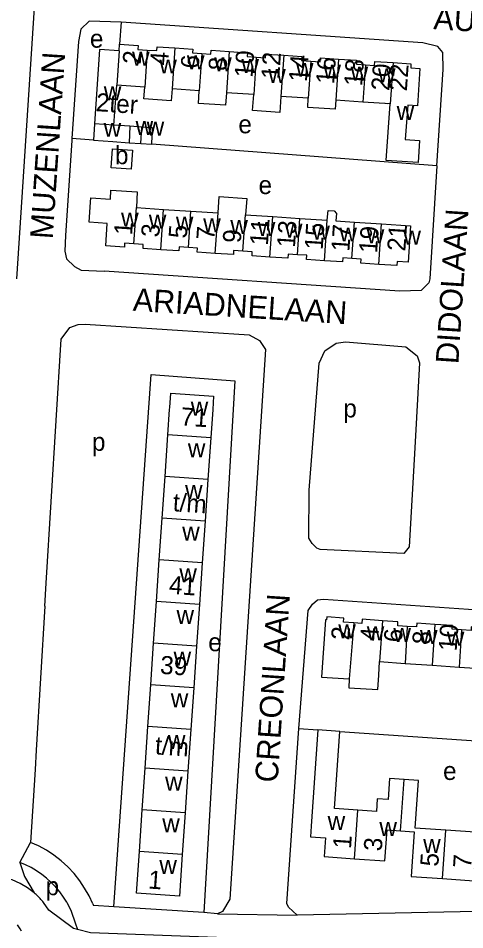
# Model space of a CAD drawing. Extents: x 161773 to 163836, y 384796 to 386521.
# Drawn here: x 162002.4 to 162100.7, y 385385.3 to 385586.3 of the extents above; entities that cross this region are included whole.
import ezdxf

# ---------------------------------------------------------------- set-up
doc = ezdxf.new("R2010")
doc.units = 0
for name, color, linetype in [('BLT_Basislijn', 7, 'Continuous'), ('BLT_Bebouwing', 7, 'Continuous'), ('BLT_Centroide', 7, 'Continuous'), ('BLT_Huisnummer', 7, 'Continuous'), ('BLT_Huisnummer_ tussenligend', 7, 'Continuous'), ('BLT_Huisnummer_reeks', 7, 'Continuous'), ('BLT_Onderverdeling_panden', 7, 'Continuous'), ('BLT_Straatnaam', 7, 'Continuous'), ('BLT_Vlakafsluiter', 7, 'Continuous')]:
    doc.layers.add(name, color=color, linetype=linetype)

msp = doc.modelspace()

# ---------------------------------------------------------------- linework, layer by layer
at = {"layer": 'BLT_Basislijn'}
for p, q in [((162004.37, 385563.74), (162007.72, 385615.15)), ((162025.03, 385585.36), (162024.69, 385580.55)), ((162002.06, 385528.83), (162004.37, 385563.74)), ((162018.97, 385559.37), (162014.2, 385559.72)), ((162094.55, 385553.73), (162031.76, 385558.48)), ((162008.23, 385456.63), (162008.52, 385461.7)), ((162008.23, 385456.63), (162006.32, 385424.91)), ((162073.2, 385429.05), (162127.39, 385425.34)), ((162006.32, 385424.91), (162006.08, 385420.68)), ((162002.72, 385400.17), (162005.11, 385404.6)), ((162018.8, 385391.02), (162018.95, 385390.66)), ((162023.43, 385390.38), (162018.95, 385390.66)), ((162043.26, 385389.11), (162023.43, 385390.38)), ((162046.22, 385388.83), (162043.26, 385389.11))]:
    msp.add_line(p, q, dxfattribs=at)
for points in [[(162018.01, 385585.6), (162016.15, 385583.89), (162015.63, 385581.16), (162014.2, 385559.72)], [(162025.03, 385585.36), (162018.01, 385585.6)], [(162094.55, 385553.73), (162095.96, 385574.96), (162095.86, 385578.74), (162094.75, 385580), (162091.46, 385580.82), (162025.03, 385585.36)], [(162014.2, 385559.72), (162014.17, 385559.29), (162012.77, 385538.38), (162012.65, 385534.92), (162013.04, 385533.24), (162014.77, 385531.53)], [(162094.55, 385553.73), (162093.01, 385528.84), (162092.75, 385527.97), (162091.07, 385526.25), (162086.42, 385526.11), (162021.27, 385530.48)], [(162014.77, 385531.53), (162016.26, 385530.74), (162021.27, 385530.48)], [(162013.71, 385518.12), (162015.56, 385518.77), (162017.12, 385518.86), (162053.25, 385516.44), (162055.5, 385515.2), (162056.85, 385513.23), (162048.99, 385392.08), (162047.36, 385389.35), (162046.22, 385388.83)], [(162008.52, 385461.7), (162011.84, 385515.49), (162013.71, 385518.12)], [(162089.67, 385491.56), (162088.45, 385469.72), (162087.24, 385468.29), (162068.83, 385469.12), (162068.1, 385469.43), (162067.07, 385470.45), (162066.35, 385471.63), (162066.46, 385482.25), (162068.61, 385510.24), (162069.91, 385512.97), (162072.36, 385514.63), (162074.4, 385514.96), (162087.72, 385513.82), (162090.2, 385511.86), (162090.71, 385510.3), (162089.67, 385491.56)], [(162023.43, 385390.38), (162031.62, 385507.71), (162050.1, 385506.35), (162043.26, 385389.11)], [(162064.18, 385429.67), (162066.19, 385455.73), (162067.14, 385457.13), (162068.27, 385458.04), (162069.62, 385458.2), (162127.01, 385454.24)], [(162064.22, 385430.27), (162064.26, 385430.84)], [(162063.81, 385388.58), (162061.9, 385390.31), (162061.53, 385391.1), (162064.18, 385429.67)], [(162064.18, 385429.67), (162068.37, 385429.39)], [(162006.08, 385420.68), (162005.11, 385404.6)], [(162018.8, 385391.02), (162017.98, 385392.78), (162017.01, 385394.5), (162015.91, 385396.14), (162014.67, 385397.7), (162013.3, 385399.17), (162011.82, 385400.52), (162010.25, 385401.75), (162008.6, 385402.84), (162006.88, 385403.8), (162005.11, 385404.6)], [(162002.72, 385400.17), (162003.8, 385397.07), (162005.91, 385393.48)], [(162013.05, 385391.39), (162012.33, 385392.54), (162011.52, 385393.66), (162010.63, 385394.72), (162009.67, 385395.73), (162008.64, 385396.67), (162007.55, 385397.53), (162006.4, 385398.32), (162005.21, 385399.03), (162003.98, 385399.64), (162002.72, 385400.17)], [(162007.98, 385391.37), (162007.78, 385391.59), (162007.59, 385391.81), (162007.39, 385392.03), (162007.19, 385392.25), (162006.98, 385392.46), (162006.77, 385392.67), (162006.56, 385392.88), (162006.35, 385393.08), (162006.13, 385393.28), (162005.91, 385393.48)], [(162015.46, 385385.35), (162014.55, 385385.57), (162009.14, 385389.66), (162007.98, 385391.37)], [(162013.05, 385391.39), (162014.03, 385389.42), (162014.93, 385386.86), (162015.46, 385385.35)], [(162491.39, 385389.88), (162477.53, 385388.68), (162443.23, 385388.4), (162414.61, 385388.14), (162283.63, 385386.13), (162154.1, 385384.19), (162114.46, 385383.57), (162055.94, 385383.24), (162018.32, 385384.67), (162015.46, 385385.35)], [(162124.85, 385389.78), (162063.81, 385388.58)], [(162003.09, 385385.02), (162002.84, 385385.5), (162002.54, 385385.97), (162002.21, 385386.43)]]:
    msp.add_lwpolyline(points, dxfattribs=at)
at = {"layer": 'BLT_Bebouwing'}
for p, q in [((162024.59, 385579.07), (162024.69, 385580.55)), ((162023.46, 385562.69), (162024.07, 385571.51)), ((162030.24, 385571.09), (162024.07, 385571.51)), ((162042.22, 385570.26), (162036.26, 385570.67)), ((162054.23, 385569.44), (162048.22, 385569.85)), ((162066.24, 385568.61), (162060.22, 385569.03)), ((162078.27, 385567.79), (162072.28, 385568.2)), ((162084.29, 385567.38), (162078.27, 385567.79)), ((162019.2, 385562.99), (162018.97, 385559.37)), ((162026.98, 385562.44), (162023.46, 385562.69)), ((162018.97, 385559.37), (162023.22, 385559.07)), ((162023.22, 385559.07), (162026.8, 385558.82)), ((162026.8, 385558.82), (162029.39, 385558.64)), ((162029.39, 385558.64), (162031.76, 385558.48)), ((162028.4, 385544.54), (162034.4, 385544.13)), ((162034.4, 385544.13), (162040.38, 385543.73)), ((162040.38, 385543.73), (162046.37, 385543.33)), ((162052.4, 385542.93), (162058.4, 385542.53)), ((162058.4, 385542.53), (162064.39, 385542.12)), ((162064.39, 385542.12), (162070.4, 385541.72)), ((162076.38, 385541.32), (162082.37, 385540.92)), ((162034.7, 385485.23), (162035.33, 385494.41)), ((162044.77, 385493.77), (162044.15, 385484.58)), ((162034.07, 385476.04), (162034.7, 385485.23)), ((162044.15, 385484.58), (162043.52, 385475.4)), ((162033.44, 385466.86), (162034.07, 385476.04)), ((162043.52, 385475.4), (162042.89, 385466.21)), ((162032.81, 385457.67), (162033.44, 385466.86)), ((162042.89, 385466.21), (162042.26, 385457.02)), ((162032.19, 385448.48), (162032.81, 385457.67)), ((162042.26, 385457.02), (162041.63, 385447.84)), ((162031.56, 385439.3), (162032.19, 385448.48)), ((162041.63, 385447.84), (162041.01, 385438.65)), ((162081.95, 385444.43), (162087.55, 385444.05)), ((162087.55, 385444.05), (162093.5, 385443.65)), ((162093.5, 385443.65), (162099.45, 385443.24)), ((162099.45, 385443.24), (162105.49, 385442.84)), ((162030.93, 385430.11), (162031.56, 385439.3)), ((162041.01, 385438.65), (162040.38, 385429.47)), ((162030.3, 385420.93), (162030.93, 385430.11)), ((162040.38, 385429.47), (162039.75, 385420.28)), ((162029.68, 385411.74), (162030.3, 385420.93)), ((162039.75, 385420.28), (162039.12, 385411.09)), ((162029.05, 385402.55), (162029.68, 385411.74)), ((162039.12, 385411.09), (162038.5, 385401.91)), ((162069.76, 385401.46), (162076.43, 385401))]:
    msp.add_line(p, q, dxfattribs=at)
for points in [[(162024.59, 385579.07), (162020.27, 385579.37), (162019.2, 385562.99)], [(162024.69, 385580.55), (162028.77, 385580.27), (162028.71, 385579.4), (162030.8, 385579.26)], [(162030.8, 385579.26), (162032.88, 385579.12), (162032.94, 385579.99), (162036.88, 385579.72)], [(162036.88, 385579.72), (162040.81, 385579.45), (162040.76, 385578.63), (162042.78, 385578.49)], [(162042.78, 385578.49), (162044.81, 385578.35), (162044.86, 385579.21), (162048.85, 385578.93)], [(162048.85, 385578.93), (162052.83, 385578.66), (162052.77, 385577.8), (162054.8, 385577.67)], [(162054.8, 385577.67), (162056.82, 385577.53), (162056.88, 385578.37), (162060.84, 385578.1)], [(162060.84, 385578.1), (162064.8, 385577.83), (162064.74, 385576.94), (162066.8, 385576.8)], [(162066.8, 385576.8), (162068.86, 385576.66), (162068.92, 385577.55), (162072.9, 385577.27)], [(162072.9, 385577.27), (162076.88, 385577), (162076.82, 385576.12), (162078.83, 385575.98)], [(162078.83, 385575.98), (162080.85, 385575.84), (162080.91, 385576.74), (162084.9, 385576.47)], [(162084.9, 385576.47), (162088.85, 385576.19), (162088.79, 385575.32), (162090.83, 385575.18), (162090.28, 385566.97), (162088.14, 385567.11), (162087.6, 385559.55), (162090.75, 385559.32), (162090.4, 385554.43), (162083.42, 385554.93), (162084.29, 385567.38)], [(162036.26, 385570.67), (162036.05, 385568.05), (162030.04, 385568.46), (162030.24, 385571.09)], [(162048.22, 385569.85), (162048.03, 385567.07), (162042.07, 385567.44), (162042.22, 385570.26)], [(162060.22, 385569.03), (162059.98, 385565.51), (162053.99, 385565.92), (162054.23, 385569.44)], [(162072.28, 385568.2), (162072.19, 385566.22), (162066.16, 385566.55), (162066.24, 385568.61)], [(162083.72, 385567.42), (162083.23, 385567.45)], [(162029.63, 385562.26), (162026.98, 385562.44)], [(162031.76, 385558.48), (162031.93, 385562.1), (162029.63, 385562.26)], [(162021.65, 385536.07), (162021.98, 385541.02), (162017.97, 385541.29), (162018.27, 385545.74), (162018.35, 385546.64), (162022.67, 385546.37), (162022.76, 385548.36)], [(162022.76, 385548.36), (162028.56, 385548), (162028.4, 385544.54)], [(162046.37, 385543.33), (162046.64, 385546.96), (162052.69, 385546.55), (162052.4, 385542.93)], [(162070.4, 385541.72), (162070.63, 385543.88), (162071.91, 385543.79), (162072.45, 385543.25), (162072.33, 385541.59), (162076.38, 385541.32)], [(162082.37, 385540.92), (162088.74, 385540.49), (162088.2, 385532.46), (162085.79, 385532.63), (162085.73, 385531.74), (162081.77, 385532.01)], [(162027.86, 385536.54), (162025.81, 385536.68), (162025.75, 385535.8), (162021.65, 385536.07)], [(162033.81, 385535.24), (162029.86, 385535.51), (162029.92, 385536.41), (162027.86, 385536.54)], [(162039.85, 385535.74), (162037.82, 385535.88), (162037.76, 385534.98), (162033.81, 385535.24)], [(162045.77, 385534.43), (162041.81, 385534.69), (162041.87, 385535.61), (162039.85, 385535.74)], [(162051.86, 385534.93), (162049.8, 385535.07), (162049.74, 385534.16), (162045.77, 385534.43)], [(162057.8, 385533.62), (162053.86, 385533.88), (162053.92, 385534.8), (162051.86, 385534.93)], [(162063.86, 385534.14), (162061.8, 385534.27), (162061.74, 385533.35), (162057.8, 385533.62)], [(162069.81, 385532.8), (162065.85, 385533.07), (162065.92, 385534), (162063.86, 385534.14)], [(162075.84, 385533.29), (162073.82, 385533.43), (162073.76, 385532.54), (162069.81, 385532.8)], [(162081.77, 385532.01), (162077.81, 385532.27), (162077.87, 385533.16), (162075.84, 385533.29)], [(162035.33, 385494.41), (162035.71, 385500), (162035.74, 385500.42), (162035.95, 385503.59), (162045.4, 385502.95), (162045.2, 385500), (162044.77, 385493.77)], [(162076.24, 385452.96), (162074.02, 385453.11), (162074.08, 385454.03), (162070.31, 385454.29), (162070.26, 385453.64), (162070, 385453.65), (162069.43, 385445.27), (162069.15, 385441.02), (162075.27, 385440.61)], [(162082.56, 385453.46), (162078.12, 385453.76), (162078.06, 385452.84), (162076.24, 385452.96)], [(162087.98, 385452.21), (162085.92, 385452.35), (162085.98, 385453.23), (162082.56, 385453.46)], [(162094.1, 385452.63), (162090.12, 385452.9), (162090.07, 385452.07), (162087.98, 385452.21)], [(162099.97, 385451.43), (162097.93, 385451.56), (162097.99, 385452.37), (162094.1, 385452.63)], [(162106.08, 385451.83), (162102.12, 385452.1), (162102.06, 385451.29), (162099.97, 385451.43)], [(162075.27, 385440.61), (162075.17, 385438.65), (162081.54, 385438.3), (162081.75, 385441.43), (162081.95, 385444.43)], [(162068.37, 385429.39), (162066.9, 385408.19)], [(162073.2, 385429.05), (162068.37, 385429.39)], [(162077.17, 385411.68), (162072.02, 385412.04), (162073.2, 385429.05)], [(162087.34, 385418.48), (162084.15, 385418.7), (162083.83, 385414.03), (162081.43, 385414.19), (162081.24, 385411.4), (162077.17, 385411.68)], [(162096.5, 385407.27), (162089.8, 385407.73), (162090.52, 385418.26), (162087.34, 385418.48)], [(162107.11, 385417.16), (162103.74, 385417.39), (162103, 385406.81), (162096.5, 385407.27)], [(162066.9, 385408.19), (162066.74, 385405.8), (162070.04, 385405.57), (162069.76, 385401.46)], [(162076.43, 385401), (162083.1, 385400.54), (162083.57, 385407.34), (162086.56, 385407.14)], [(162086.56, 385407.14), (162089.54, 385406.93), (162088.86, 385397.09), (162095.76, 385396.61)], [(162095.76, 385396.61), (162102.66, 385396.13), (162103.34, 385405.92), (162106.32, 385405.72)], [(162038.5, 385401.91), (162037.87, 385392.72), (162028.42, 385393.37), (162029.05, 385402.55)]]:
    msp.add_lwpolyline(points, dxfattribs=at)
msp.add_lwpolyline([(162023.11, 385557.48), (162027.52, 385557.2), (162027.25, 385552.99), (162022.84, 385553.27)], close=True, dxfattribs=at)
at = {"layer": 'BLT_Onderverdeling_panden'}
for p, q in [((162024.59, 385579.07), (162024.07, 385571.51)), ((162030.8, 385579.26), (162030.24, 385571.09)), ((162036.88, 385579.72), (162036.26, 385570.67)), ((162048.85, 385578.93), (162048.22, 385569.85)), ((162042.78, 385578.49), (162042.22, 385570.26)), ((162054.8, 385577.67), (162054.23, 385569.44)), ((162060.84, 385578.1), (162060.22, 385569.03)), ((162066.8, 385576.8), (162066.24, 385568.61)), ((162072.9, 385577.27), (162072.28, 385568.2)), ((162078.83, 385575.98), (162078.27, 385567.79)), ((162084.9, 385576.47), (162084.29, 385567.38)), ((162023.46, 385562.69), (162019.2, 385562.99)), ((162026.98, 385562.44), (162026.8, 385558.82)), ((162029.39, 385558.64), (162029.63, 385562.26)), ((162027.86, 385536.54), (162028.4, 385544.54)), ((162033.81, 385535.24), (162034.4, 385544.13)), ((162039.85, 385535.74), (162040.38, 385543.73)), ((162045.77, 385534.43), (162046.37, 385543.33)), ((162051.86, 385534.93), (162052.4, 385542.93)), ((162057.8, 385533.62), (162058.4, 385542.53)), ((162063.86, 385534.14), (162064.39, 385542.12)), ((162069.81, 385532.8), (162070.4, 385541.72)), ((162075.84, 385533.29), (162076.38, 385541.32)), ((162081.77, 385532.01), (162082.37, 385540.92)), ((162044.77, 385493.77), (162035.33, 385494.41)), ((162044.15, 385484.58), (162034.7, 385485.23)), ((162043.52, 385475.4), (162034.07, 385476.04)), ((162042.89, 385466.21), (162033.44, 385466.86)), ((162042.26, 385457.02), (162032.81, 385457.67)), ((162076.24, 385452.96), (162075.27, 385440.61)), ((162082.56, 385453.46), (162081.95, 385444.43)), ((162087.98, 385452.21), (162087.55, 385444.05)), ((162094.1, 385452.63), (162093.5, 385443.65)), ((162099.97, 385451.43), (162099.45, 385443.24)), ((162041.63, 385447.84), (162032.19, 385448.48)), ((162041.01, 385438.65), (162031.56, 385439.3)), ((162040.38, 385429.47), (162030.93, 385430.11)), ((162039.75, 385420.28), (162030.3, 385420.93)), ((162086.56, 385407.14), (162087.34, 385418.48)), ((162039.12, 385411.09), (162029.68, 385411.74)), ((162076.43, 385401), (162077.17, 385411.68)), ((162095.76, 385396.61), (162096.5, 385407.27)), ((162038.5, 385401.91), (162029.05, 385402.55))]:
    msp.add_line(p, q, dxfattribs=at)
at = {"layer": 'BLT_Vlakafsluiter'}
msp.add_line((162046.22, 385388.83), (162063.81, 385388.58), dxfattribs=at)
msp.add_lwpolyline([(162005.91, 385393.48), (162004.44, 385394.58), (162002.82, 385395.54), (162001.05, 385396.31), (161999.17, 385396.87), (161997.23, 385397.2), (161995.26, 385397.29), (161993.3, 385397.14), (161991.41, 385396.76), (161989.62, 385396.18), (161987.95, 385395.41)], dxfattribs=at)

# ---------------------------------------------------------------- texts
at = {"layer": 'BLT_Centroide'}
for s, p in [('e', (162018.17, 385579.77)), ('w', (162027.44, 385575.81)), ('w', (162033.45, 385574.09)), ('w', (162039.52, 385574.98)), ('w', (162045.53, 385574.59)), ('w', (162051.52, 385574.19)), ('w', (162057.42, 385572.02)), ('w', (162063.52, 385573.36)), ('w', (162069.56, 385572.94)), ('w', (162075.56, 385572.53)), ('w', (162081.58, 385572.12)), ('w', (162021.22, 385568.15)), ('w', (162085.7, 385563.86)), ('w', (162021.19, 385560.12)), ('w', (162028.22, 385560.53)), ('w', (162030.66, 385560.38)), ('e', (162050.85, 385560.9)), ('b', (162023.68, 385554.09)), ('e', (162055.29, 385547.5)), ('w', (162025.03, 385540.3)), ('w', (162031.14, 385539.89)), ('w', (162037.09, 385539.48)), ('w', (162043.11, 385539.08)), ('w', (162049.08, 385538.69)), ('w', (162055.12, 385538.27)), ('w', (162061.09, 385537.88)), ('w', (162067.12, 385537.45)), ('w', (162073.09, 385537.06)), ('w', (162079.11, 385536.66)), ('w', (162087.17, 385536.34)), ('w', (162040.36, 385498.69)), ('p', (162073.96, 385498.27)), ('p', (162018.61, 385490.9)), ('w', (162039.73, 385489.5)), ('w', (162039.11, 385480.31)), ('w', (162038.48, 385471.12)), ('w', (162037.85, 385461.94)), ('w', (162037.23, 385452.75)), ('w', (162072.84, 385449.58)), ('w', (162079.12, 385449.16)), ('w', (162084.97, 385448.75)), ('w', (162090.83, 385448.33)), ('w', (162096.73, 385447.95)), ('e', (162044.21, 385446.73)), ('w', (162036.59, 385443.56)), ('w', (162035.97, 385434.38)), ('w', (162035.34, 385425.19)), ('e', (162095.91, 385418.35)), ('w', (162034.71, 385416)), ('w', (162034.09, 385406.81)), ('w', (162070.5, 385407.32)), ('w', (162081.89, 385405.98)), ('w', (162091.53, 385402.27)), ('w', (162033.45, 385397.62)), ('p', (162008.42, 385392.94))]:
    msp.add_text(s, height=4, dxfattribs=at).set_placement(p)
at = {"layer": 'BLT_Huisnummer'}
for s, rotation, p in [('2', 86.0808, (162029.34, 385576.02)), ('10', 86.0778, (162053.96, 385573.08)), ('6', 86.0773, (162042.12, 385575.06)), ('14', 86.0772, (162065.92, 385572.13)), ('18', 86.0782, (162078.09, 385571.21)), ('22', 86.0278, (162087.93, 385570.11)), ('2ter', 356.015, (162019.39, 385565.8)), ('1', 86.1769, (162027.44, 385538.34)), ('5', 86.1641, (162039.46, 385537.64)), ('13', 86.1697, (162063.29, 385535.61)), ('17', 86.1741, (162075.27, 385534.74)), ('21', 86.1741, (162087.59, 385534.81)), ('9', 86.1663, (162051.37, 385536.62)), ('4', 86.1358, (162081.62, 385448.88)), ('8', 86.136, (162093.1, 385448.1)), ('1', 86.0383, (162075.63, 385403.1)), ('5', 86.0375, (162094.84, 385399.17))]:
    msp.add_text(s, height=4, rotation=rotation, dxfattribs=at).set_placement(p)
at = {"layer": 'BLT_Huisnummer_ tussenligend'}
for s, rotation, p in [('4', 86.0808, (162035.36, 385575.79)), ('12', 86.0778, (162059.83, 385572.73)), ('8', 86.0773, (162048.23, 385574.59)), ('16', 86.0772, (162071.92, 385571.65)), ('20', 86.0782, (162084.07, 385570.19)), ('3', 86.1769, (162033.41, 385537.89)), ('11', 86.1663, (162057.34, 385536.08)), ('15', 86.1697, (162069.4, 385535.14)), ('7', 86.1641, (162045.57, 385537.27)), ('19', 86.1741, (162081.38, 385534.39)), ('10', 86.1323, (162098.89, 385446.65)), ('2', 86.1358, (162075.24, 385449.07)), ('6', 86.136, (162086.84, 385448.61)), ('3', 86.0383, (162082.41, 385402.56)), ('7', 86.0375, (162102.08, 385398.81))]:
    msp.add_text(s, height=4, rotation=rotation, dxfattribs=at).set_placement(p)
at = {"layer": 'BLT_Huisnummer_reeks'}
for s, rotation, p in [('71', 356.0898, (162038.05, 385496.51)), ('t/m', 356.0898, (162036.33, 385477.62)), ('41', 356.0894, (162035.48, 385459.41)), ('39', 356.0894, (162033.53, 385441.76)), ('t/m', 356.0894, (162032.41, 385424.02)), ('1', 356.0889, (162030.92, 385394.43))]:
    msp.add_text(s, height=4, rotation=rotation, dxfattribs=at).set_placement(p)
at = {"layer": 'BLT_Straatnaam'}
for s, rotation, p in [('AULISLAAN', 356.2653, (162093.7, 385583.87)), ('MUZENLAAN', 86.1745, (162009.97, 385537.48)), ('DIDOLAAN', 86.241, (162099.27, 385509.94)), ('ARIADNELAAN', 356.385, (162027.53, 385521.79)), ('CREONLAAN', 86.2751, (162059.49, 385417.67))]:
    msp.add_text(s, height=5, rotation=rotation, dxfattribs=at).set_placement(p)

doc.saveas('drawing.dxf')
